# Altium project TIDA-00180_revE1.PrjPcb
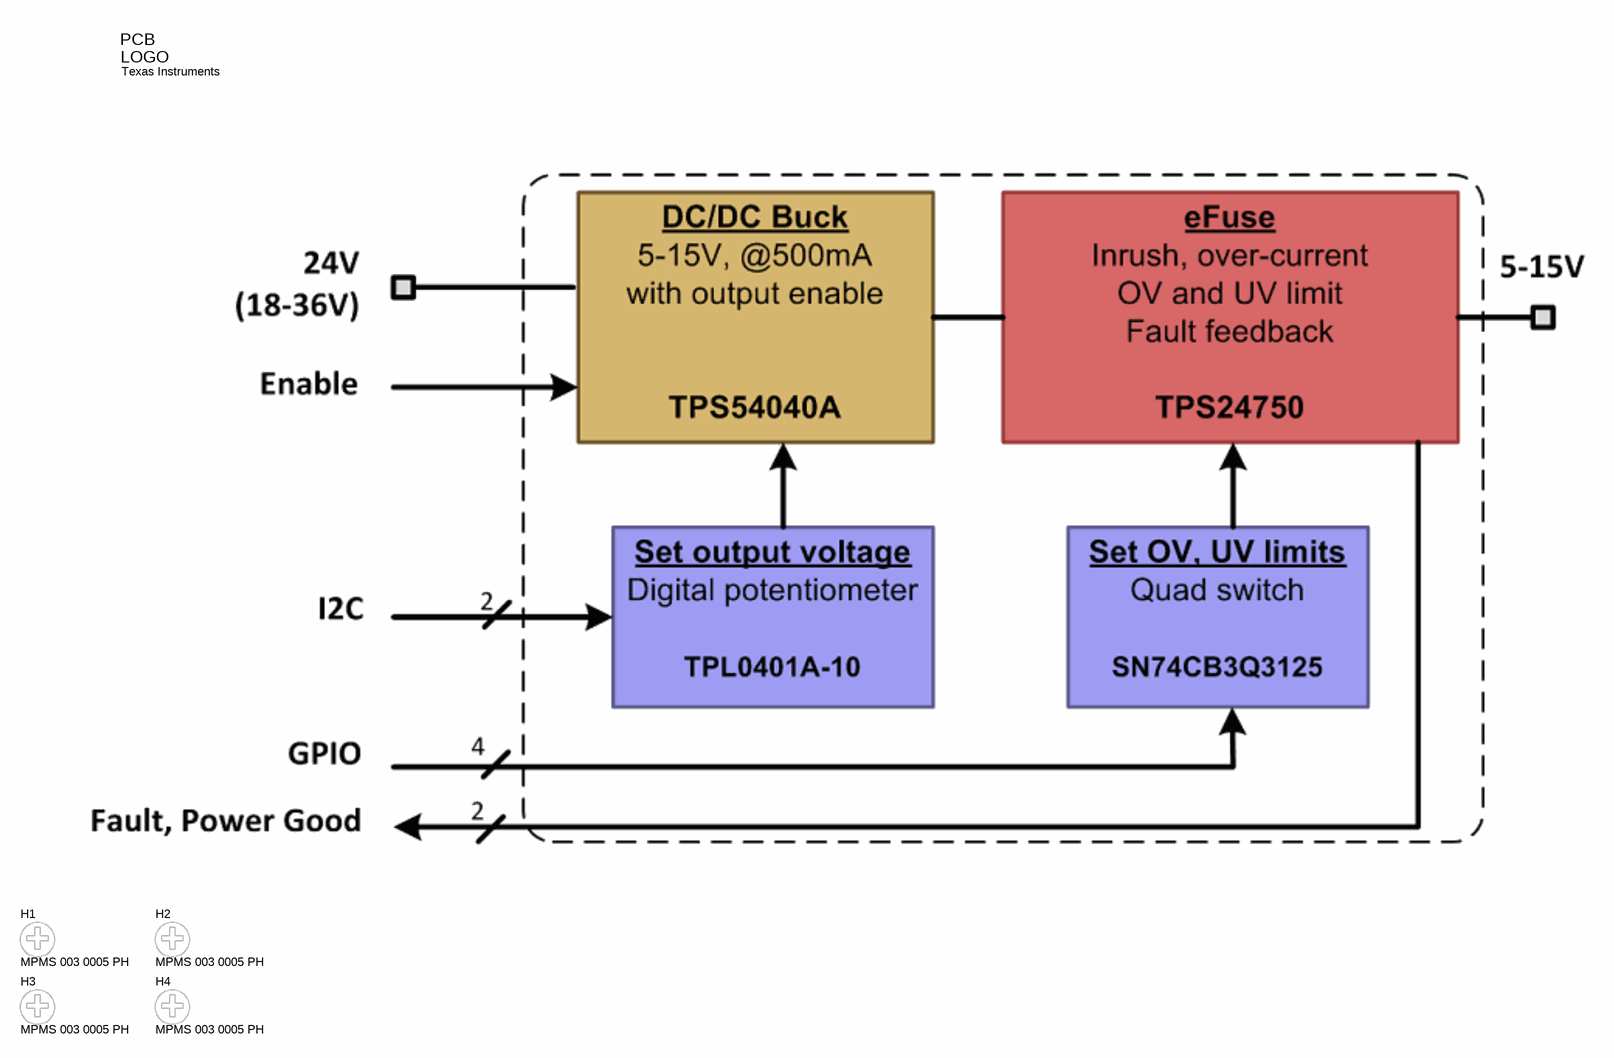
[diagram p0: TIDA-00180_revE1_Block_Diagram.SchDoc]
TechSupport: http://www.ti.com/support; SCH_Rev: E1; PRJ_Title: P/S with programmable output and protection; PRJ_Number: TIDA-00180; PRJ_Engineer: Stauder/Staebler; PRJ_Customer: Public Release; PCB_Rev: E1; PCB_Layout: Stauder; CopyrightYear: 2014
3 sheets, 92 parts. Net scope: global (net labels, ports and power ports of the same name join across sheets).
Board file: TIDA-00180_revE1_PCB.PcbDoc
Sheets:
  TIDA-00180_revE1_Block_Diagram.SchDoc
  TIDA-00180_revE1_PS.SchDoc
  TIDA-00180_revE1_PR.SchDoc

## Sheet TIDA-00180_revE1_Block_Diagram.SchDoc
size 431 x 279 mm; Date: Not shown in title block; ApprovedBy: Not shown in title block; CheckedBy: Not shown in title block; Author: Not shown in title block; CompanyName: Not shown in title block; Engineer: Not shown in title block; Organization: Not shown in title block; Address1: Not shown in title block; Address2: Not shown in title block; Address3: Not shown in title block; Address4: Not shown in title block; DocumentNumber: 1; Revision: Use project parameter SCH_Rev; SheetNumber: 1; SheetTotal: 4; PageSetup: Record=PageOptions|CenterHorizontal=True|CenterVertical=True|PrintScale=1.00|XCorrection=1.00|YCorrection=1.00|PrintKind=0|BorderSize=5000000|LeftOffset=0|BottomOffset=0|Orientation=2|PaperLength=1000|PaperWidth=1000|Scale=100|PaperSource=15|PrintQuality=600|MediaType=1|DitherType=10|PaperKind=Letter|PrintScaleMode=1

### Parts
H1  MPMS 003 0005 PH  [BuildingFastener_MPMS_003_0005_PH]
H2  MPMS 003 0005 PH  [BuildingFastener_MPMS_003_0005_PH]
H3  MPMS 003 0005 PH  [BuildingFastener_MPMS_003_0005_PH]
H4  MPMS 003 0005 PH  [BuildingFastener_MPMS_003_0005_PH]
Logo1  Texas Instruments  [TI_Stacked_Overlay_Small]  (no BOM)

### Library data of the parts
H1-H4 = MPMS 003 0005 PH: MACHINE SCREW PAN PHILLIPS M3 5mm; Manufacturer: B&F Fastener Supply; CompType: Hardware
Logo1 = TI_Logo: Texas Instrument Corporate Signature; SymbolCreator: a0412235

## Sheet TIDA-00180_revE1_PS.SchDoc
size 431 x 279 mm; Date: Not shown in title block; ApprovedBy: Not shown in title block; CheckedBy: Not shown in title block; Author: Not shown in title block; CompanyName: Not shown in title block; Engineer: Not shown in title block; Organization: Not shown in title block; Address1: Not shown in title block; Address2: Not shown in title block; Address3: Not shown in title block; Address4: Not shown in title block; DocumentNumber: 2; Revision: Use project parameter SCH_Rev; SheetNumber: 2; SheetTotal: 4; PageSetup: Record=PageOptions|CenterHorizontal=True|CenterVertical=True|PrintScale=0.62|XCorrection=1.00|YCorrection=1.00|PrintKind=0|BorderSize=5000000|LeftOffset=0|BottomOffset=0|Orientation=2|PaperLength=1000|PaperWidth=1000|Scale=100|PaperSource=15|PrintQuality=600|MediaType=1|DitherType=10|PaperKind=Letter|PrintScaleMode=1
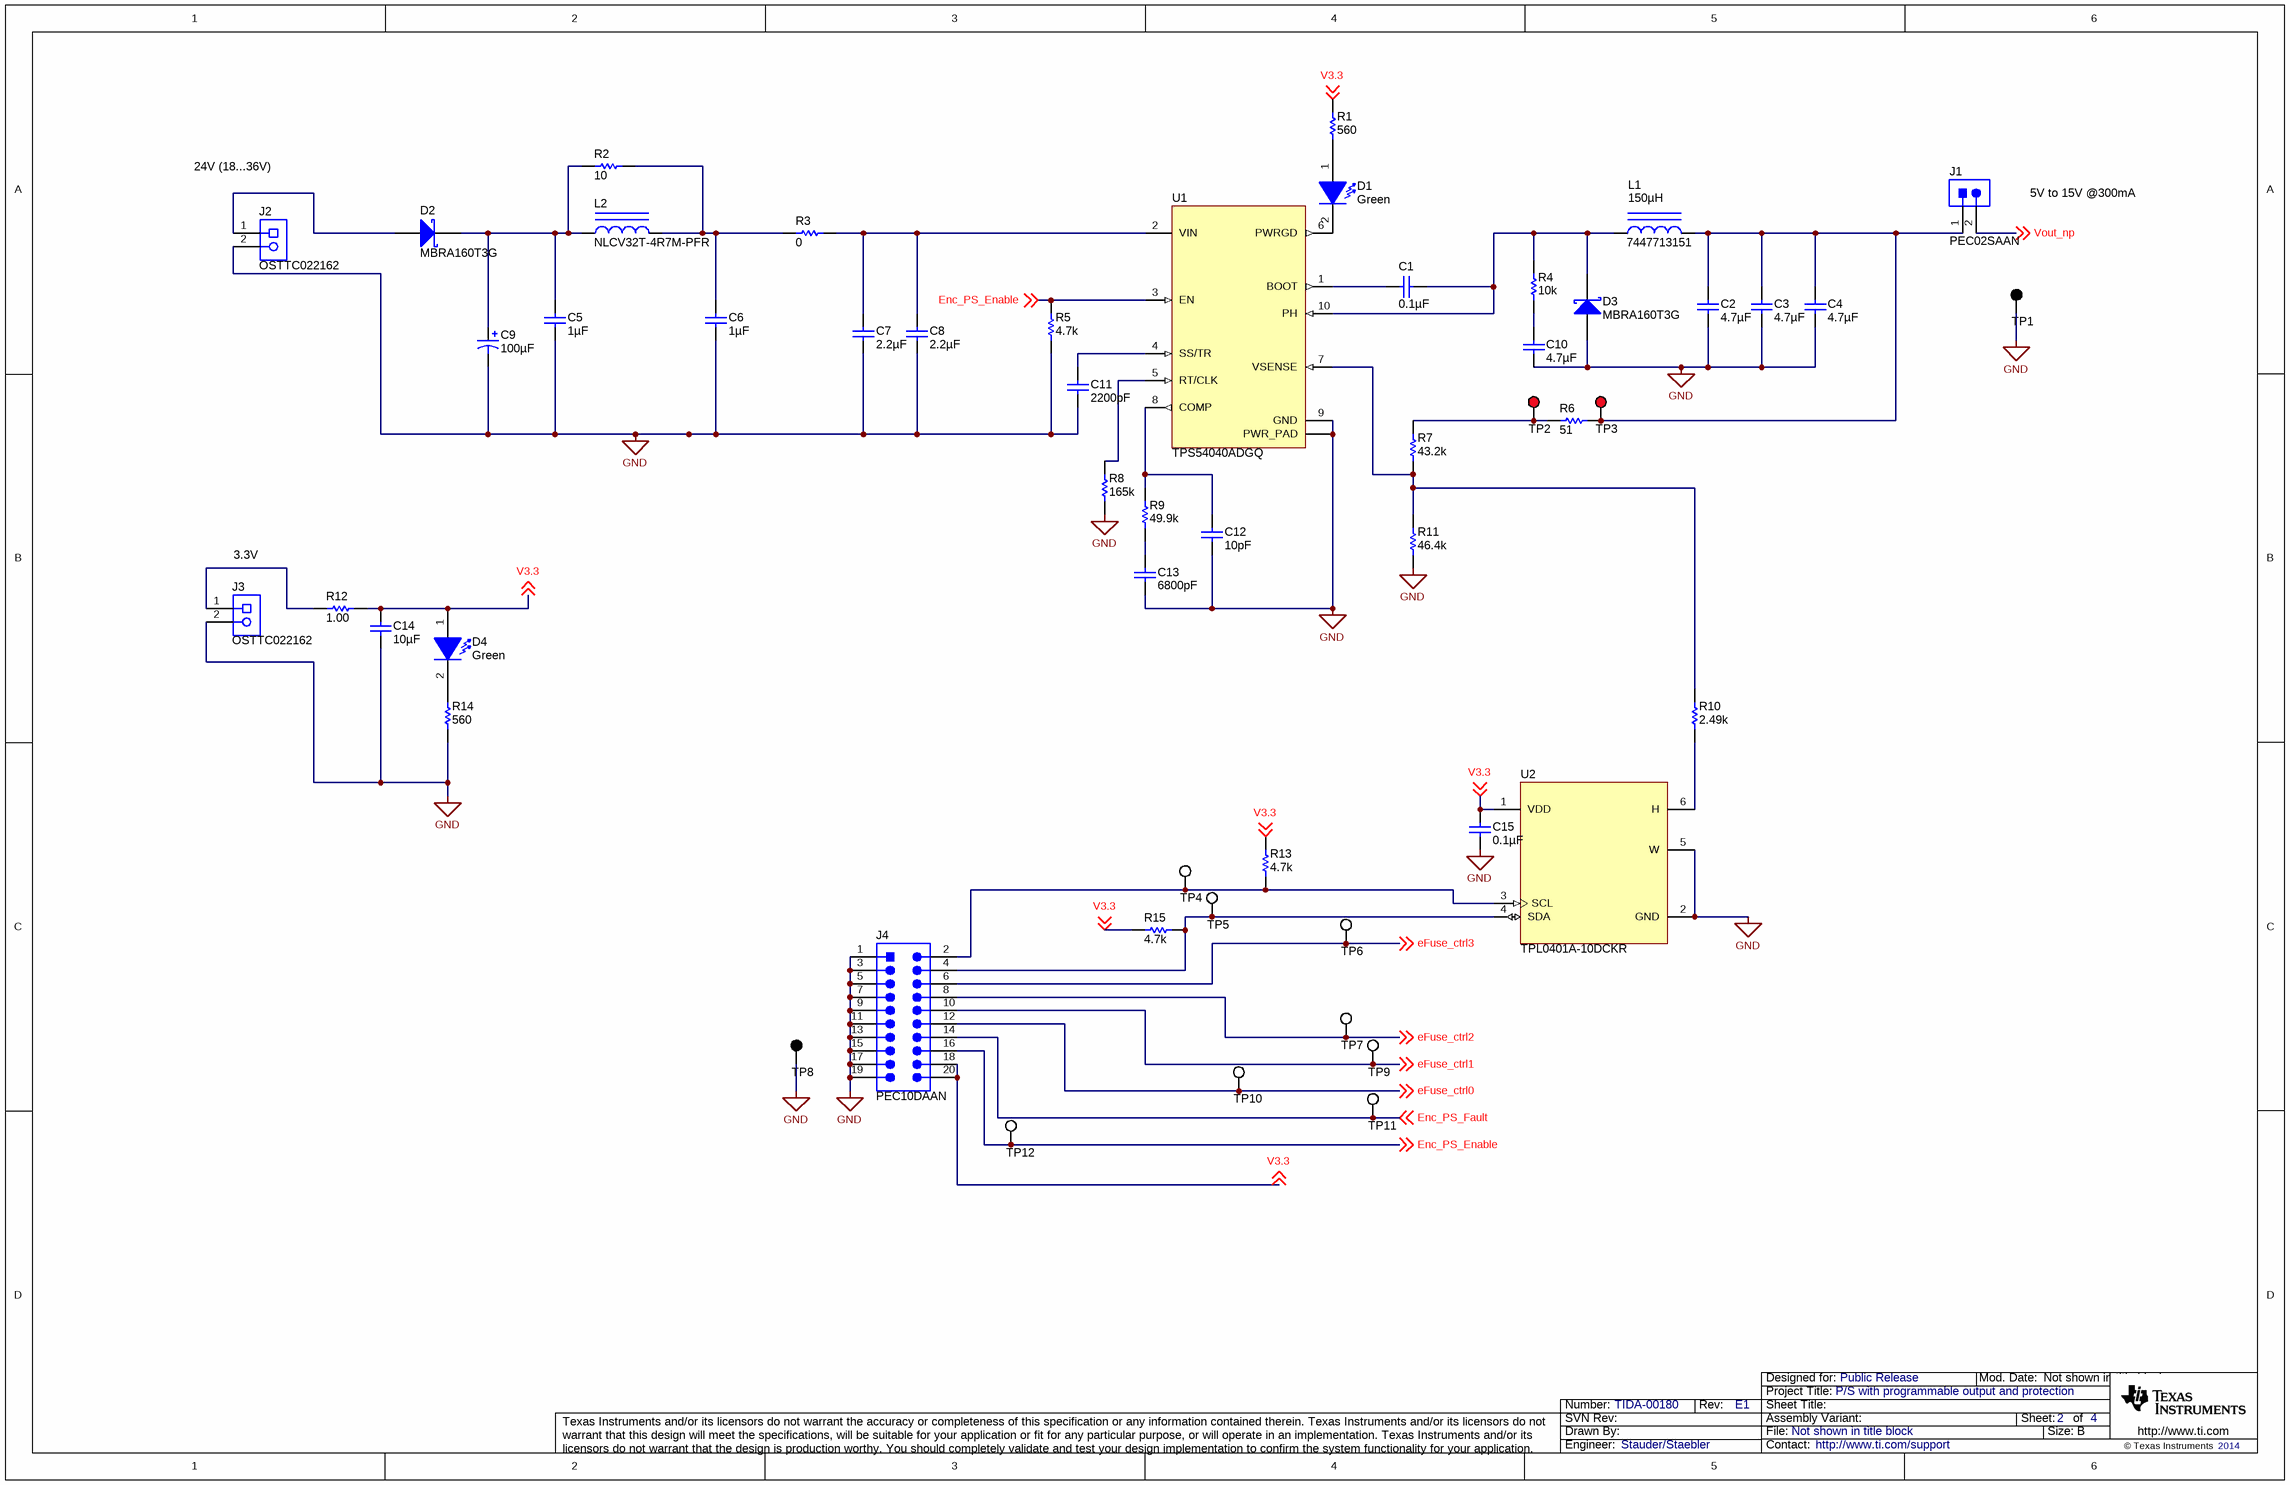
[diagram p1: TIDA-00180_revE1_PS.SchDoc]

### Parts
C1  ValueDisplayed: 0.1µF  [0603]  (hidden comment: GRM188R71H104KA93D)
C2  ValueDisplayed: 4.7µF  [0805_HV]  (hidden comment: C2012X5R1H475K125AB)
C3  ValueDisplayed: 4.7µF  [0805_HV]  (hidden comment: C2012X5R1H475K125AB)
C4  ValueDisplayed: 4.7µF  [0805_HV]  (hidden comment: C2012X5R1H475K125AB)
C5  ValueDisplayed: 1µF  [0805_HV]  (hidden comment: GRM21BR71H105KA12L)
C6  ValueDisplayed: 1µF  [0805_HV]  (hidden comment: GRM21BR71H105KA12L)
C7  ValueDisplayed: 2.2µF  [1206]  (hidden comment: GRM31CR61H225KA88L)
C8  ValueDisplayed: 2.2µF  [1206]  (hidden comment: GRM31CR61H225KA88L)
C9  ValueDisplayed: 100µF  [SM_RADIAL_G]  (hidden comment: EEE-FK1J101P)
C10  ValueDisplayed: 4.7µF  [0805_HV]  (hidden comment: C2012X5R1H475K125AB)
C11  ValueDisplayed: 2200pF  [0603]  (hidden comment: GRM188R71C222KA01D)
C12  ValueDisplayed: 10pF  [0603]  (hidden comment: GRM1885C1H100JA01D)
C13  ValueDisplayed: 6800pF  [0603]  (hidden comment: GRM188R71E682KA01D)
C14  ValueDisplayed: 10µF  [0805_HV]  (hidden comment: C2012X5R1E106K125AB)
C15  ValueDisplayed: 0.1µF  [0603]  (hidden comment: 06033D104KAT2A)
D1  value Green  [LG L29K_GREEN]  (hidden comment: LG L29K-G2J1-24-Z)
D2  MBRA160T3G  [SMA]
D3  MBRA160T3G  [SMA]
D4  value Green  [LG L29K_GREEN]  (hidden comment: LG L29K-G2J1-24-Z)
J1  PEC02SAAN  [CONN_PEC02SAAN]
J2  OSTTC022162  [On-Shore_OSTTC022162]
J3  OSTTC022162  [On-Shore_OSTTC022162]
J4  PEC10DAAN  [SULLINS_PEC10DAAN]
L1  7447713151  ValueDisplayed: 150µH  [WE-PD-1030]
L2  NLCV32T-4R7M-PFR  [NLCV32]
R1  ValueDisplayed: 560  [0603]  (hidden comment: CRCW0603560RJNEA)
R2  value 10  [0603]  (hidden comment: CRCW060310R0JNEAHP)
R3  value 0  [0603]  (hidden comment: CRCW06030000Z0EA)
R4  value 10k  [0805_HV]  (hidden comment: CRCW080510K0JNEA)
R5  value 4.7k  [0603]  (hidden comment: CRCW06034K70JNEA)
R6  value 51  [0603]  (hidden comment: CRCW060351R0JNEA)
R7  ValueDisplayed: 43.2k  [0603]  (hidden comment: CRCW060343K2FKEA)
R8  value 165k  [0603]  (hidden comment: CRCW0603165KFKEA)
R9  ValueDisplayed: 49.9k  [0603]  (hidden comment: CRCW060349K9FKEA)
R10  ValueDisplayed: 2.49k  [0603]  (hidden comment: CRCW06032K49FKEA)
R11  ValueDisplayed: 46.4k  [0603]  (hidden comment: CRCW060346K4FKEA)
R12  ValueDisplayed: 1.00  [0603]  (hidden comment: CRCW06031R00FKEA)
R13  value 4.7k  [0603]  (hidden comment: CRCW06034K70JNEA)
R14  ValueDisplayed: 560  [0603]  (hidden comment: CRCW0603560RJNEA)
R15  value 4.7k  [0603]  (hidden comment: CRCW06034K70JNEA)
TP1  5001  [Keystone5001]  (value not drawn)
TP2  5000  [Keystone5000]  (value not drawn)
TP3  5000  [Keystone5000]  (value not drawn)
TP4  5002  [Keystone5002]  (value not drawn)
TP5  5002  [Keystone5002]  (value not drawn)
TP6  5002  [Keystone5002]  (value not drawn)
TP7  5002  [Keystone5002]  (value not drawn)
TP8  5001  [Keystone5001]  (value not drawn)
TP9  5002  [Keystone5002]  (value not drawn)
TP10  5002  [Keystone5002]  (value not drawn)
TP11  5002  [Keystone5002]  (value not drawn)
TP12  5002  [Keystone5002]  (value not drawn)
U1  TPS54040ADGQ  [DGQ0010D_N]
U2  TPL0401A-10DCKR  [DCK0006A_N]

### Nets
GND: C2.2 C3.2 C4.2 C5.2 C6.2 C7.2 C8.2 C9.2(-) C10.2 C11.2 C12.2 C13.2 C14.2 C15.2 D3.2(A) J2.2 J3.2 J4.1 J4.3 J4.5 J4.7 J4.9 J4.11 J4.13 J4.15 J4.17 J4.19 R5.2 R8.1 R11.1 R14.1 TP1.1 TP8.1 U1.9(GND) U1.11(PWR_PAD) U2.2(GND) U2.5(W)
eFuse_ctrl0: J4.12 TP10.1 ; off-sheet eFuse_ctrl0
eFuse_ctrl1: J4.10 TP9.1 ; off-sheet eFuse_ctrl1
eFuse_ctrl2: J4.8 TP7.1 ; off-sheet eFuse_ctrl2
eFuse_ctrl3: J4.6 TP6.1 ; off-sheet eFuse_ctrl3
Enc_PS_Enable: J4.16 R5.1 TP12.1 U1.3(EN) ; off-sheet Enc_PS_Enable
Enc_PS_Fault: J4.14 TP11.1 ; off-sheet Enc_PS_Fault
V3.3: C14.1 C15.1 D4.1(A) J4.18 J4.20 R1.2 R12.2 R13.1 R15.2 U2.1(VDD) ; off-sheet V3.3
Vout_np: J1.2 ; off-sheet Vout_np
NetC1_1: C1.1 D3.1(K) L1.1 R4.2 U1.10(PH)
NetC1_2: C1.2 U1.1(BOOT)
NetC2_1: C2.1 C3.1 C4.1 J1.1 L1.2 R6.1 TP3.1
NetC5_1: C5.1 C9.1(+) D2.1(K) L2.1 R2.1
NetC6_1: C6.1 L2.2 R2.2 R3.1
NetC7_1: C7.1 C8.1 R3.2 U1.2(VIN)
NetC10_1: C10.1 R4.1
NetC11_1: C11.1 U1.4(SS/TR)
NetC12_1: C12.1 R9.2 U1.8(COMP)
NetC13_1: C13.1 R9.1
NetD1_1: D1.1(A) R1.1
NetD1_2: D1.2(K) U1.6(PWRGD)
NetD2_2: D2.2(A) J2.1
NetD4_2: D4.2(K) R14.2
NetJ3_1: J3.1 R12.1
NetJ4_2: J4.2 R13.2 TP4.1 U2.3(SCL)
NetJ4_4: J4.4 R15.1 TP5.1 U2.4(SDA)
NetR6_2: R6.2 R7.2 TP2.1
NetR7_1: R7.1 R10.2 R11.2 U1.7(VSENSE)
NetR8_2: R8.2 U1.5(RT/CLK)
NetR10_1: R10.1 U2.6(H)

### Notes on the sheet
- 24V (18...36V)
- 5V to 15V @300mA
- (near J3) 3.3V

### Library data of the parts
C1 = GRM188R71H104KA93D: CAP, CERM, 0.1 µF, 50 V, +/- 10%, X7R, 0603; Manufacturer: MuRata; Polarized: N; CompType: Capacitor; Value: 0.1uF; U/M: EA; Cap_F: 0.0000001; Tolerance_%: 10; Value1: Unknown; VDC_V: 50; Value2: 50V; TaMin_C: -55; TaMax_C: 125
C2-C4 C10 = C2012X5R1H475K125AB: CAP, CERM, 4.7 µF, 50 V, +/- 10%, X5R, 0805; Manufacturer: TDK; Polarized: N; CompType: Capacitor; Value: 4.7uF; U/M: EA; Cap_F: 0.0000047; Tolerance_%: 10; Value1: Unknown; VDC_V: 50; Value2: 50V; TaMin_C: -55; TaMax_C: 85; Cap_Case: 0805
C5 C6 = GRM21BR71H105KA12L: CAP, CERM, 1uF, 50V, +/-10%, X7R, 0805; Manufacturer: MuRata; Polarized: N; CompType: Capacitor; U/M: EA; Cap_F: 0.000001; Tolerance_%: 10; Value1: Unknown; VDC_V: 50; TaMin_C: -55; TaMax_C: 125; Cap_Case: 0805
C7 C8 = GRM31CR61H225KA88L: CAP, CERM, 2.2uF, 50V, +/-10%, X5R, 1206; Manufacturer: MuRata; Polarized: N; CompType: Capacitor; U/M: EA; Cap_F: 0.0000022; Tolerance_%: 10; Value1: Unknown; VDC_V: 50; TaMin_C: -55; TaMax_C: 85
C9 = EEE-FK1J101P: CAP, AL, 100uF, 63V, +/-20%, 0.35 ohm, SMD; Manufacturer: Panasonic; Polarized: Y; CompType: Capacitor; U/M: EA; Cap_F: 0.0001; Tolerance_%: 20; VDC_V: 63; ESR_Ohm: 0.35; IRMS_A: 0.4; TaMin_C: -55; TaMax_C: 105; Cap_Case: G
C11 = GRM188R71C222KA01D: CAP, CERM, 2200pF, 16V, +/-10%, X7R, 0603; Manufacturer: MuRata; Polarized: N; CompType: Capacitor; U/M: EA; Cap_F: 0.0000000022; Tolerance_%: 10; Value1: Unknown; VDC_V: 16; TaMin_C: -55; TaMax_C: 125
C12 = GRM1885C1H100JA01D: CAP, CERM, 10 pF, 50 V, +/- 5%, C0G/NP0, 0603; Manufacturer: MuRata; Polarized: N; CompType: Capacitor; Value: 10pF; U/M: EA; Cap_F: 0.00000000001; Tolerance_%: 5; Value1: Unknown; VDC_V: 50; Value2: 50V; TaMin_C: -55; TaMax_C: 125
C13 = GRM188R71E682KA01D: CAP, CERM, 6800 pF, 25 V, +/- 10%, X7R, 0603; Manufacturer: MuRata; Polarized: N; CompType: Capacitor; Value: 6800pF; U/M: EA; Cap_F: 0.0000000068; Tolerance_%: 10; Value1: Unknown; VDC_V: 25; Value2: 25V; TaMin_C: -55; TaMax_C: 125
C14 = C2012X5R1E106K125AB: CAP, CERM, 10uF, 25V, +/-10%, X5R, 0805; Manufacturer: TDK; Polarized: N; CompType: Capacitor; U/M: EA; Cap_F: 0.00001; Tolerance_%: 10; Value1: Unknown; VDC_V: 25; TaMin_C: -55; TaMax_C: 85; Cap_Case: 0805
C15 = 06033D104KAT2A: CAP, CERM, 0.1uF, 25V, +/-10%, X5R, 0603; Manufacturer: AVX; Polarized: N; CompType: Capacitor; U/M: EA; Cap_F: 0.0000001; Tolerance_%: 10; ESR_Ohm: 0.048; Value1: 0.048 ohm; VDC_V: 25; IRMS_A: 0.53; TaMin_C: -55; TaMax_C: 85
D1 D4 = LG L29K-G2J1-24-Z: LED, Green, SMD; Manufacturer: OSRAM; Vf_V: 1.7; Value2: 1.7V; Io_A: 0.002; Tjmax_C: 110; Value1: W; U/M: EA
D2 D3 = MBRA160T3G: Diode, Schottky, 60V, 1A, SMA; Manufacturer: ON Semiconductor; U/M: EA; Vf_V: 0.51; Value2: 0.51V; Io_A: 1; Vr_V: 60; TJmax_C: 150; RJC_CperW: 35
J1 = PEC02SAAN: Header, 100mil, 2x1, Tin plated, TH; Manufacturer: Sullins Connector Solutions; SymbolCreator: a0412235; U/M: EA
J2 J3 = OSTTC022162: Terminal Block, 2-pole, 200mil, TH; Manufacturer: On-Shore Technology; SymbolCreator: a0412235; U/M: EA
J4 = PEC10DAAN: Header, 10x2, 2.54mm, TH; Manufacturer: Sullins Connector Solutions; SymbolCreator: a0412235; U/M: EA
L1 = 7447713151: Inductor, Shielded Drum Core, Ferrite, 150uH, 0.7A, 0.57 ohm, SMD; Manufacturer: Wurth Elektronik eiSos; Ind_H: 150.0E-6; Imax_A: 0.7; Irms: 0.7A @ 40C rise; Isat: 1.1A @ 10% inductance drop; DCR_ohm: 0.57; U/M: EA
L2 = NLCV32T-4R7M-PFR: Inductor, Wirewound, Ferrite, 4.7uH, 0.9A, 0.2 ohm, SMD; Manufacturer: TDK; Ind_H: 4.7E-6; ValueDisplayed: 4.7µH; Imax_A: 0.9; Irms: 0.9A @ 20C rise; Isat: 0.9A @ 10% inductance drop; DCR_ohm: 0.2; Value1: 0.2 ohm; U/M: EA
R1 R14 = CRCW0603560RJNEA: RES, 560, 5%, 0.1 W, 0603; Manufacturer: Vishay-Dale; CompType: Resistor; Value: 560; Value_Code: 560R; Tolerance_%: 5; Power_W: 0.1; Value2: 0.1W; VDC_V: 75; TempCo: 200 ppm/C; EIA_Code: E24; U/M: EA
R2 = CRCW060310R0JNEAHP: RES, 10 ohm, 5%, 0.25W, 0603; Manufacturer: Vishay-Dale; CompType: Resistor; Value_Code: 10R0; Tolerance_%: 5; Power_W: 0.25; VDC_V: 75; TempCo: 200 ppm/C; EIA_Code: E24; U/M: EA
R3 = CRCW06030000Z0EA: RES, 0 ohm, 5%, 0.1W, 0603; Manufacturer: Vishay-Dale; CompType: Resistor; Value_Code: 0000; Tolerance_%: 5; Power_W: 0.1; VDC_V: 75; TempCo: 200 ppm/C; EIA_Code: E24; U/M: EA
R4 = CRCW080510K0JNEA: RES, 10k ohm, 5%, 0.125W, 0805; Manufacturer: Vishay-Dale; CompType: Resistor; Res_ohm: 10000; Value_Code: 10k0; Tolerance_%: 5; Power_W: 0.125; VDC_V: 150; TempCo: 200 ppm/C; EIA_Code: E24; U/M: EA
R5 R13 R15 = CRCW06034K70JNEA: RES, 4.7k ohm, 5%, 0.1W, 0603; Manufacturer: Vishay-Dale; CompType: Resistor; Res_ohm: 4700; Value_Code: 4k70; Tolerance_%: 5; Power_W: 0.1; VDC_V: 75; TempCo: 200 ppm/C; EIA_Code: E24; U/M: EA
R6 = CRCW060351R0JNEA: RES, 51 ohm, 5%, 0.1W, 0603; Manufacturer: Vishay-Dale; CompType: Resistor; Value_Code: 51R0; Tolerance_%: 5; Power_W: 0.1; VDC_V: 75; TempCo: 200 ppm/C; EIA_Code: E24; U/M: EA
R7 = CRCW060343K2FKEA: RES, 43.2 k, 1%, 0.1 W, 0603; Manufacturer: Vishay-Dale; CompType: Resistor; Res_ohm: 43200; Value: 43.2k; Value_Code: 43k2; Tolerance_%: 1; Power_W: 0.1; Value2: 0.1W; VDC_V: 75; TempCo: 100 ppm/C; EIA_Code: E96; U/M: EA
R8 = CRCW0603165KFKEA: RES, 165k ohm, 1%, 0.1W, 0603; Manufacturer: Vishay-Dale; CompType: Resistor; Res_ohm: 165000; Tolerance_%: 1; Power_W: 0.1; VDC_V: 75; TempCo: 100 ppm/C; EIA_Code: E96; U/M: EA
R9 = CRCW060349K9FKEA: RES, 49.9 k, 1%, 0.1 W, 0603; Manufacturer: Vishay-Dale; CompType: Resistor; Res_ohm: 49900; Value: 49.9k; Value_Code: 49k9; Tolerance_%: 1; Power_W: 0.1; Value2: 0.1W; VDC_V: 75; TempCo: 100 ppm/C; EIA_Code: E96; U/M: EA
R10 = CRCW06032K49FKEA: RES, 2.49 k, 1%, 0.1 W, 0603; Manufacturer: Vishay-Dale; CompType: Resistor; Res_ohm: 2490; Value: 2.49k; Value_Code: 2k49; Tolerance_%: 1; Power_W: 0.1; Value2: 0.1W; VDC_V: 75; TempCo: 100 ppm/C; EIA_Code: E96; U/M: EA
R11 = CRCW060346K4FKEA: RES, 46.4 k, 1%, 0.1 W, 0603; Manufacturer: Vishay-Dale; CompType: Resistor; Res_ohm: 46400; Value: 46.4k; Value_Code: 46k4; Tolerance_%: 1; Power_W: 0.1; Value2: 0.1W; VDC_V: 75; TempCo: 100 ppm/C; EIA_Code: E96; U/M: EA
R12 = CRCW06031R00FKEA: RES, 1.00, 1%, 0.1 W, 0603; Manufacturer: Vishay-Dale; CompType: Resistor; Res_ohm: 1; Value: 1.00; Value_Code: 1R00; Power_W: 0.1; Value2: 0.1W; VDC_V: 75; TempCo: 100 ppm/C; EIA_Code: E96; U/M: EA
TP1 TP8 = 5001: Test Point, Miniature, Black, TH; Manufacturer: Keystone; CompType: Test Point Loop; U/M: EA
TP2 TP3 = 5000: Test Point, Miniature, Red, TH; Manufacturer: Keystone; CompType: Test Point Loop; U/M: EA
TP4-TP7 TP9-TP12 = 5002: Test Point, Miniature, White, TH; Manufacturer: Keystone; CompType: Test Point Loop; U/M: EA
U1 = TPS54040ADGQ: 0.5 A, 42 V Step Down DC/DC Converter with Eco-mode, DGQ0010D; Alternate Manufacturer: None; Manufacturer: Texas Instruments; SymbolCreator: a0411947; CompType: IC; U/M: EA
U2 = TPL0401A-10DCKR: 128 TAPS Single Channel Digital Potentiometer with I2C Interface, DCK0006A; Alternate Manufacturer: None; Manufacturer: Texas Instruments; SymbolCreator: Altium; CompType: IC; U/M: EA

## Sheet TIDA-00180_revE1_PR.SchDoc
size 431 x 279 mm; Date: Not shown in title block; ApprovedBy: Not shown in title block; CheckedBy: Not shown in title block; Author: Not shown in title block; CompanyName: Not shown in title block; Engineer: Not shown in title block; Organization: Not shown in title block; Address1: Not shown in title block; Address2: Not shown in title block; Address3: Not shown in title block; Address4: Not shown in title block; DocumentNumber: 3; Revision: Use project parameter SCH_Rev; SheetNumber: 3; SheetTotal: 4; PageSetup: Record=PageOptions|CenterHorizontal=True|CenterVertical=True|PrintScale=0.62|XCorrection=1.00|YCorrection=1.00|PrintKind=0|BorderSize=5000000|LeftOffset=0|BottomOffset=0|Orientation=2|PaperLength=1000|PaperWidth=1000|Scale=100|PaperSource=15|PrintQuality=600|MediaType=1|DitherType=10|PaperKind=Letter|PrintScaleMode=1
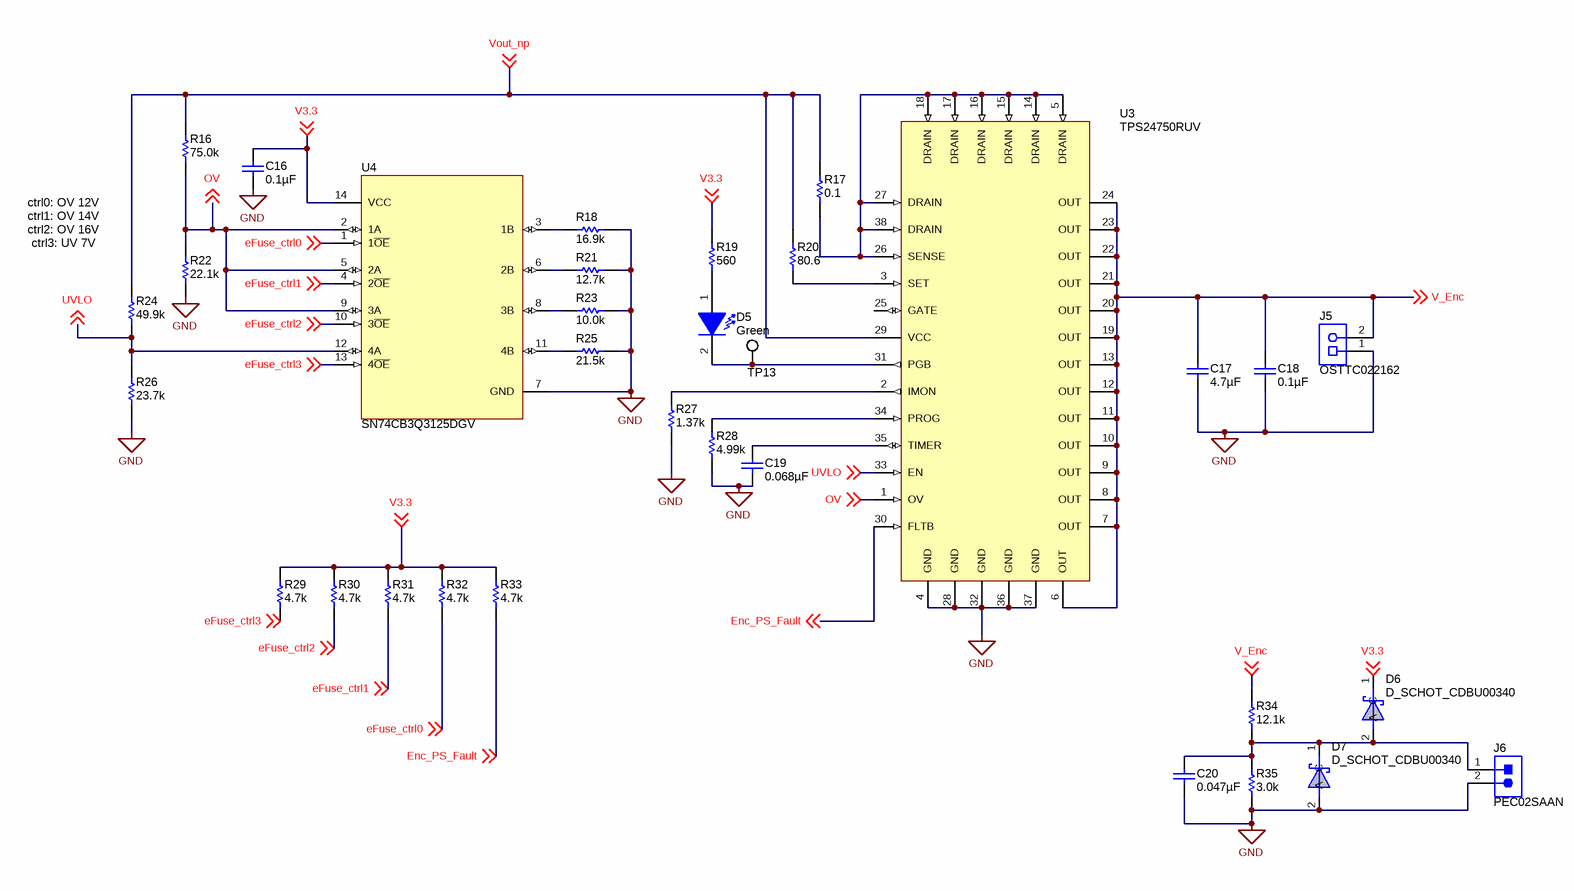
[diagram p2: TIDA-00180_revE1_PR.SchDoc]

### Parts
C16  ValueDisplayed: 0.1µF  [0603]  (hidden comment: 06033D104KAT2A)
C17  ValueDisplayed: 4.7µF  [0805_HV]  (hidden comment: C2012X5R1H475K125AB)
C18  ValueDisplayed: 0.1µF  [0603]  (hidden comment: GRM188R71H104KA93D)
C19  ValueDisplayed: 0.068µF  [0603]  (hidden comment: GRM188R71C683KA01D)
C20  ValueDisplayed: 0.047µF  [0603]  (hidden comment: GRM188R70J473KA01D)
D5  value Green  [LG L29K_GREEN]  (hidden comment: LG L29K-G2J1-24-Z)
D6  D_SCHOT_CDBU00340  [C603-DIODE]
D7  D_SCHOT_CDBU00340  [C603-DIODE]
J5  OSTTC022162  [On-Shore_OSTTC022162]
J6  PEC02SAAN  [CONN_PEC02SAAN]
R16  ValueDisplayed: 75.0k  [0603]  (hidden comment: CRCW060375K0FKEA)
R17  ValueDisplayed: 0.1  [0603]  (hidden comment: ERJ-3RSFR10V)
R18  ValueDisplayed: 16.9k  [0603]  (hidden comment: CRCW060316K9FKEA)
R19  ValueDisplayed: 560  [0603]  (hidden comment: CRCW0603560RJNEA)
R20  ValueDisplayed: 80.6  [0603]  (hidden comment: CRCW060380R6FKEA)
R21  ValueDisplayed: 12.7k  [0603]  (hidden comment: CRCW060312K7FKEA)
R22  ValueDisplayed: 22.1k  [0603]  (hidden comment: CRCW060322K1FKEA)
R23  ValueDisplayed: 10.0k  [0603]  (hidden comment: CRCW060310K0FKEA)
R24  ValueDisplayed: 49.9k  [0603]  (hidden comment: CRCW060349K9FKEA)
R25  ValueDisplayed: 21.5k  [0603]  (hidden comment: CRCW060321K5FKEA)
R26  ValueDisplayed: 23.7k  [0603]  (hidden comment: CRCW060323K7FKEA)
R27  ValueDisplayed: 1.37k  [0603]  (hidden comment: CRCW06031K37FKEA)
R28  value 4.99k  [0603]  (hidden comment: CRCW06034K99FKEA)
R29  value 4.7k  [0603]  (hidden comment: CRCW06034K70JNEA)
R30  value 4.7k  [0603]  (hidden comment: CRCW06034K70JNEA)
R31  value 4.7k  [0603]  (hidden comment: CRCW06034K70JNEA)
R32  value 4.7k  [0603]  (hidden comment: CRCW06034K70JNEA)
R33  value 4.7k  [0603]  (hidden comment: CRCW06034K70JNEA)
R34  ValueDisplayed: 12.1k  [0603]  (hidden comment: CRCW060312K1FKEA)
R35  ValueDisplayed: 3.0k  [0603]  (hidden comment: CRCW06033K00JNEA)
TP13  5002  [Keystone5002]  (value not drawn)
U3  TPS24750RUV  [RUV0036A]
U4  SN74CB3Q3125DGV  [DGV0014A_N]

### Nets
GND: C16.2 C17.2 C18.2 C19.2 C20.2 D7.2(A) J5.1 J6.2 R18.2 R21.2 R22.1 R23.2 R25.2 R26.1 R27.1 R28.1 R35.1 U3.4(GND) U3.28(GND) U3.32(GND) U3.36(GND) U3.37(GND) U4.7(GND)
eFuse_ctrl0: R32.1 U4.1(1~{OE}) ; off-sheet eFuse_ctrl0
eFuse_ctrl1: R31.1 U4.4(2~{OE}) ; off-sheet eFuse_ctrl1
eFuse_ctrl2: R30.1 U4.10(3~{OE}) ; off-sheet eFuse_ctrl2
eFuse_ctrl3: R29.1 U4.13(4~{OE}) ; off-sheet eFuse_ctrl3
Enc_PS_Fault: R33.1 U3.30(FLTB) ; off-sheet Enc_PS_Fault
OV: R16.1 R22.2 U3.1(OV) U4.2(1A) U4.5(2A) U4.9(3A) ; off-sheet OV
UVLO: R24.1 R26.2 U3.33(EN) U4.12(4A) ; off-sheet UVLO
V3.3: C16.1 D6.1(C) R19.2 R29.2 R30.2 R31.2 R32.2 R33.2 U4.14(VCC) ; off-sheet V3.3
V_Enc: C17.1 C18.1 J5.2 R34.2 U3.6(OUT) U3.7(OUT) U3.8(OUT) U3.9(OUT) U3.10(OUT) U3.11(OUT) U3.12(OUT) U3.13(OUT) U3.19(OUT) U3.20(OUT) U3.21(OUT) U3.22(OUT) U3.23(OUT) U3.24(OUT) ; off-sheet V_Enc
Vout_np: R16.2 R17.2 R20.2 R24.2 U3.29(VCC) ; off-sheet Vout_np
NetC19_1: C19.1 U3.35(TIMER)
NetC20_1: C20.1 D6.2(A) D7.1(C) J6.1 R34.1 R35.2
NetD5_1: D5.1(A) R19.1
NetD5_2: D5.2(K) TP13.1 U3.31(PGB)
NetR17_1: R17.1 U3.5(DRAIN) U3.14(DRAIN) U3.15(DRAIN) U3.16(DRAIN) U3.17(DRAIN) U3.18(DRAIN) U3.26(SENSE) U3.27(DRAIN) U3.38(DRAIN)
NetR18_1: R18.1 U4.3(1B)
NetR20_1: R20.1 U3.3(SET)
NetR21_1: R21.1 U4.6(2B)
NetR23_1: R23.1 U4.8(3B)
NetR25_1: R25.1 U4.11(4B)
NetR27_2: R27.2 U3.2(IMON)
NetR28_2: R28.2 U3.34(PROG)

Not connected (* = marked no-connect by the designer): U3 25(GATE)

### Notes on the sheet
- ctrl0: OV 12V
- ctrl1: OV 14V
- ctrl2: OV 16V
- ctrl3: UV 7V

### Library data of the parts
C16 = 06033D104KAT2A: as C15 on sheet TIDA-00180_revE1_PS
C17 = C2012X5R1H475K125AB: as C2 on sheet TIDA-00180_revE1_PS
C18 = GRM188R71H104KA93D: as C1 on sheet TIDA-00180_revE1_PS
C19 = GRM188R71C683KA01D: CAP, CERM, 0.068 µF, 16 V, +/- 10%, X7R, 0603; Manufacturer: MuRata; Polarized: N; CompType: Capacitor; Value: 0.068uF; U/M: EA; Cap_F: 0.000000068; Tolerance_%: 10; Value1: Unknown; VDC_V: 16; Value2: 16V; TaMin_C: -55; TaMax_C: 125
C20 = GRM188R70J473KA01D: CAP, CERM, 0.047 µF, 6.3 V, +/- 10%, X7R, 0603; Manufacturer: MuRata; Polarized: N; CompType: Capacitor; Value: 0.047uF; U/M: EA; Cap_F: 0.000000047; Tolerance_%: 10; Value1: Unknown; VDC_V: 6.3; Value2: 6.3V; TaMin_C: -55; TaMax_C: 125
D5 = LG L29K-G2J1-24-Z: as D1 on sheet TIDA-00180_revE1_PS
D6 D7 = D_SCHOT_CDBU00340: Diode, Schottky, 30mA, 40V; Manufacturer: Comchip; Area: 9100
J5 = OSTTC022162: as J2 on sheet TIDA-00180_revE1_PS
J6 = PEC02SAAN: as J1 on sheet TIDA-00180_revE1_PS
R16 = CRCW060375K0FKEA: RES, 75.0 k, 1%, 0.1 W, 0603; Manufacturer: Vishay-Dale; CompType: Resistor; Res_ohm: 75000; Value: 75.0k; Value_Code: 75k0; Tolerance_%: 1; Power_W: 0.1; Value2: 0.1W; VDC_V: 75; TempCo: 100 ppm/C; EIA_Code: E96; U/M: EA
R17 = ERJ-3RSFR10V: RES, 0.1, 1%, 0.1 W, 0603; Manufacturer: Panasonic; CompType: Resistor; Value: 0.1; Value_Code: R100; Tolerance_%: 1; Value2: 0.1W; TempCo: 300 ppm/C; EIA_Code: E96; U/M: EA
R18 = CRCW060316K9FKEA: RES, 16.9 k, 1%, 0.1 W, 0603; Manufacturer: Vishay-Dale; CompType: Resistor; Res_ohm: 16900; Value: 16.9k; Value_Code: 16k9; Tolerance_%: 1; Power_W: 0.1; Value2: 0.1W; VDC_V: 75; TempCo: 100 ppm/C; EIA_Code: E96; U/M: EA
R19 = CRCW0603560RJNEA: as R1 on sheet TIDA-00180_revE1_PS
R20 = CRCW060380R6FKEA: RES, 80.6, 1%, 0.1 W, 0603; Manufacturer: Vishay-Dale; CompType: Resistor; Value: 80.6; Value_Code: 80R6; Tolerance_%: 1; Power_W: 0.1; Value2: 0.1W; VDC_V: 75; TempCo: 100 ppm/C; EIA_Code: E96; U/M: EA
R21 = CRCW060312K7FKEA: RES, 12.7 k, 1%, 0.1 W, 0603; Manufacturer: Vishay-Dale; CompType: Resistor; Res_ohm: 12700; Value: 12.7k; Value_Code: 12k7; Tolerance_%: 1; Power_W: 0.1; Value2: 0.1W; VDC_V: 75; TempCo: 100 ppm/C; EIA_Code: E96; U/M: EA
R22 = CRCW060322K1FKEA: RES, 22.1 k, 1%, 0.1 W, 0603; Manufacturer: Vishay-Dale; CompType: Resistor; Res_ohm: 22100; Value: 22.1k; Value_Code: 22k1; Tolerance_%: 1; Power_W: 0.1; Value2: 0.1W; VDC_V: 75; TempCo: 100 ppm/C; EIA_Code: E96; U/M: EA
R23 = CRCW060310K0FKEA: RES, 10.0 k, 1%, 0.1 W, 0603; Manufacturer: Vishay-Dale; CompType: Resistor; Res_ohm: 10000; Value: 10.0k; Value_Code: 10k0; Tolerance_%: 1; Power_W: 0.1; Value2: 0.1W; VDC_V: 75; TempCo: 100 ppm/C; EIA_Code: E96; U/M: EA
R24 = CRCW060349K9FKEA: as R9 on sheet TIDA-00180_revE1_PS
R25 = CRCW060321K5FKEA: RES, 21.5 k, 1%, 0.1 W, 0603; Manufacturer: Vishay-Dale; CompType: Resistor; Res_ohm: 21500; Value: 21.5k; Value_Code: 21k5; Tolerance_%: 1; Power_W: 0.1; Value2: 0.1W; VDC_V: 75; TempCo: 100 ppm/C; EIA_Code: E96; U/M: EA
R26 = CRCW060323K7FKEA: RES, 23.7 k, 1%, 0.1 W, 0603; Manufacturer: Vishay-Dale; CompType: Resistor; Res_ohm: 23700; Value: 23.7k; Value_Code: 23k7; Tolerance_%: 1; Power_W: 0.1; Value2: 0.1W; VDC_V: 75; TempCo: 100 ppm/C; EIA_Code: E96; U/M: EA
R27 = CRCW06031K37FKEA: RES, 1.37 k, 1%, 0.1 W, 0603; Manufacturer: Vishay-Dale; CompType: Resistor; Res_ohm: 1370; Value: 1.37k; Value_Code: 1k37; Tolerance_%: 1; Power_W: 0.1; Value2: 0.1W; VDC_V: 75; TempCo: 100 ppm/C; EIA_Code: E96; U/M: EA
R28 = CRCW06034K99FKEA: RES, 4.99k ohm, 1%, 0.1W, 0603; Manufacturer: Vishay-Dale; CompType: Resistor; Res_ohm: 4990; Value_Code: 4k99; Tolerance_%: 1; Power_W: 0.1; VDC_V: 75; TempCo: 100 ppm/C; EIA_Code: E96; U/M: EA
R29-R33 = CRCW06034K70JNEA: as R5 on sheet TIDA-00180_revE1_PS
R34 = CRCW060312K1FKEA: RES, 12.1 k, 1%, 0.1 W, 0603; Manufacturer: Vishay-Dale; CompType: Resistor; Res_ohm: 12100; Value: 12.1k; Value_Code: 12k1; Tolerance_%: 1; Power_W: 0.1; Value2: 0.1W; VDC_V: 75; TempCo: 100 ppm/C; EIA_Code: E96; U/M: EA
R35 = CRCW06033K00JNEA: RES, 3.0 k, 5%, 0.1 W, 0603; Manufacturer: Vishay-Dale; CompType: Resistor; Res_ohm: 3000; Value: 3.0k; Value_Code: 3k00; Tolerance_%: 5; Power_W: 0.1; Value2: 0.1W; VDC_V: 75; TempCo: 200 ppm/C; EIA_Code: E24; U/M: EA
TP13 = 5002: as TP4 on sheet TIDA-00180_revE1_PS
U3 = TPS24750RUV: 2.5 to 18 V Positive Voltage 10A Integrated Hot-Swap Controller, RUV0036A; Alternate Manufacturer: None; Manufacturer: Texas Instruments; SymbolCreator: a0411947; CompType: IC; U/M: EA
U4 = SN74CB3Q3125DGV: Quadruple FET Bus Switch, 2.5-V/3.3-V Low-Voltage High-Bandwidth Bus Switch, DGV0014A; Alternate Manufacturer: None; Manufacturer: Texas Instruments; SymbolCreator: Altium; CompType: IC; U/M: EA

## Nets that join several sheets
GND: TIDA-00180_revE1_PS (37 pins), TIDA-00180_revE1_PR (23 pins)
eFuse_ctrl0: TIDA-00180_revE1_PS (J4.12 TP10.1), TIDA-00180_revE1_PR (R32.1 U4.1)
eFuse_ctrl1: TIDA-00180_revE1_PS (J4.10 TP9.1), TIDA-00180_revE1_PR (R31.1 U4.4)
eFuse_ctrl2: TIDA-00180_revE1_PS (J4.8 TP7.1), TIDA-00180_revE1_PR (R30.1 U4.10)
eFuse_ctrl3: TIDA-00180_revE1_PS (J4.6 TP6.1), TIDA-00180_revE1_PR (R29.1 U4.13)
Enc_PS_Fault: TIDA-00180_revE1_PS (J4.14 TP11.1), TIDA-00180_revE1_PR (R33.1 U3.30)
V3.3: TIDA-00180_revE1_PS (10 pins), TIDA-00180_revE1_PR (9 pins)
Vout_np: TIDA-00180_revE1_PS (J1.2), TIDA-00180_revE1_PR (5 pins)

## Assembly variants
TIDA-00180_revE1-Complete: all parts fitted
TIDA-00180_revE1: not fitted C10 C20 D6 D7 J6 R4 R34 R35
